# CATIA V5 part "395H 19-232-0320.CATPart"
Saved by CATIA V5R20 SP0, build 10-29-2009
Part number: 395H 19-232-0320
Source: Unknown
Bounding box of the stored display mesh (mm): x -30.125 to 30.125, y -30.125 to 30.125, z -100 to 20
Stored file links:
  C:\Users\Utente\Desktop\3D files 395H FCA\395H 19-232-0320.CATPart
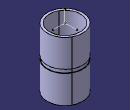
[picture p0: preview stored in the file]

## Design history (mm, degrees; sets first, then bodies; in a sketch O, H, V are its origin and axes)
Set1
  Line1 to Line3: stored without definition
  Point1 "Punto.4": stored without definition
Body1 (main body)
  Solid1 "PartBody": solid without history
